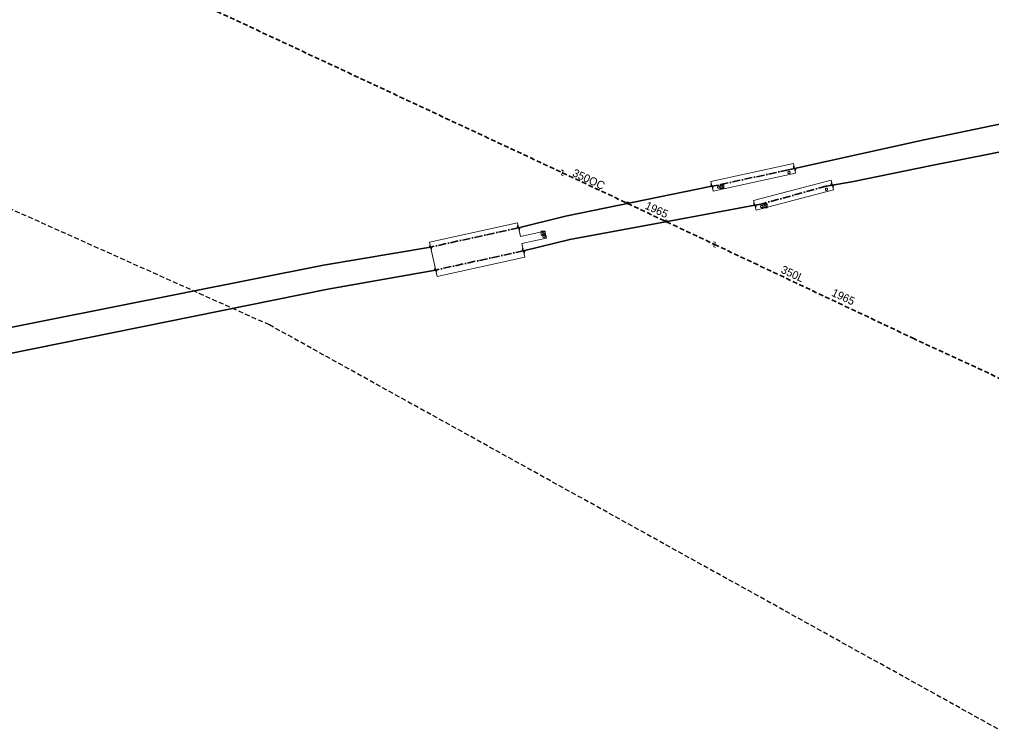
# Model space of a CAD drawing. Extents: x -735085 to -733500, y -1044153 to -1043402.
# Drawn here: x -734295.8 to -734101.4, y -1043978.5 to -1043837.5 of the extents above; entities that cross this region are included whole.
import ezdxf

# ---------------------------------------------------------------- set-up
doc = ezdxf.new("R2010")
doc.units = 0
doc.header["$LTSCALE"] = 0.32
doc.linetypes.add('DOT_DASHED', pattern=[7.7, 5, -1.2, 0.3, -1.2])
doc.linetypes.add('MEDIUM_DASHED', pattern=[4.5, 3, -1.5])
doc.layers.add('15', color=7, linetype='Continuous')
doc.layers.add('63', color=7, linetype='MEDIUM_DASHED', lineweight=25)
doc.layers.add('8', color=7, linetype='Continuous', lineweight=13)

msp = doc.modelspace()

# ---------------------------------------------------------------- linework, layer by layer
at = {"layer": '63'}
msp.add_lwpolyline([(-733848.634, -1044145.724), (-734009.504, -1044029.598), (-734245.816, -1043898.575), (-734359.738, -1043847.543)], dxfattribs=at)
at = {"layer": '8', "linetype": 'MEDIUM_DASHED', "lineweight": 35}
msp.add_line((-734187.217, -1043868.148), (-734156.787, -1043882.494), dxfattribs=at)
at = {"layer": '8', "linetype": 'DOT_DASHED', "lineweight": 35}
for p, q in [((-734196, -1043879.15), (-734213.581, -1043883.01)), ((-734194.993, -1043883.74), (-734212.574, -1043887.601))]:
    msp.add_line(p, q, dxfattribs=at)
at = {"layer": '8', "linetype": 'MEDIUM_DASHED', "lineweight": 35}
for points in [[(-734536.445, -1043703.656), (-734437.539, -1043750.071), (-734375.002, -1043779.659), (-734325.456, -1043803.606), (-734187.217, -1043868.148)], [(-734156.787, -1043882.494), (-734117.203, -1043901.187), (-734043.806, -1043935.179), (-734015.348, -1043948.221), (-733950.381, -1043983.651), (-733846.87, -1044026.74)]]:
    msp.add_lwpolyline(points, dxfattribs=at)
at = {"layer": '8', "lineweight": 35}
for points in [[(-733500.14, -1043736.5), (-733578.17, -1043751.88), (-733749.774, -1043785.92), (-733782.129, -1043791.12), (-733828.849, -1043802.13), (-733843.715, -1043805.114), (-734013.309, -1043840.11), (-734084.403, -1043855.21), (-734114.903, -1043861.54), (-734140.791, -1043867.289)], [(-733499.8, -1043741.34), (-733577.602, -1043756.92), (-733749.741, -1043791.62), (-733780.166, -1043797.47), (-733830.039, -1043807.22), (-733842.373, -1043809.844), (-733894.938, -1043820.77), (-733957.55, -1043834.01), (-734011.796, -1043845.47), (-734062.127, -1043856.17), (-734083.072, -1043860.7), (-734113.399, -1043866.69), (-734129.342, -1043869.95), (-734133.254, -1043870.63)], [(-734157.313, -1043870.86), (-734186.633, -1043876.84), (-734196, -1043879.15)], [(-734148.727, -1043874.66), (-734162.243, -1043877.147), (-734185.761, -1043881.48), (-734194.991, -1043883.74)], [(-734213.581, -1043883.01), (-734235.013, -1043886.65), (-734347.918, -1043909.08), (-734406.037, -1043923.44), (-734576.715, -1043958.74), (-734576.97, -1043958.792)], [(-734212.574, -1043887.6), (-734234.101, -1043891.43), (-734346.778, -1043914.23), (-734403.784, -1043928.54), (-734524.885, -1043953.44), (-734575.754, -1043964.068), (-734576.02, -1043964.124)]]:
    msp.add_lwpolyline(points, dxfattribs=at)
at = {"layer": '8'}
for points in [[(-734187.432, -1043867.587), (-734187.038, -1043867.771), (-734187.406, -1043868.557), (-734187.012, -1043868.741)], [(-734141.037, -1043867.266), (-734140.988, -1043866.827), (-734140.608, -1043867.714), (-734140.53, -1043867.316)], [(-734157.558, -1043870.832), (-734157.501, -1043870.393), (-734157.136, -1043871.287), (-734157.051, -1043870.89)], [(-734155.474, -1043871.104), (-734155.464, -1043871.147), (-734155.442, -1043871.186), (-734155.411, -1043871.217), (-734155.373, -1043871.238), (-734155.33, -1043871.249), (-734155.286, -1043871.247), (-734155.244, -1043871.234), (-734155.207, -1043871.21), (-734155.178, -1043871.177), (-734155.159, -1043871.137), (-734155.151, -1043871.094), (-734155.155, -1043871.05), (-734155.171, -1043871.009), (-734155.197, -1043870.974), (-734155.232, -1043870.947), (-734155.273, -1043870.93), (-734155.299, -1043870.925)], [(-734155.152, -1043870.767), (-734155.157, -1043870.724), (-734155.174, -1043870.683), (-734155.201, -1043870.649), (-734155.237, -1043870.623), (-734155.278, -1043870.608), (-734155.321, -1043870.605), (-734155.364, -1043870.613), (-734155.403, -1043870.633), (-734155.436, -1043870.662), (-734155.459, -1043870.7), (-734155.471, -1043870.742), (-734155.472, -1043870.785), (-734155.46, -1043870.828), (-734155.438, -1043870.865), (-734155.406, -1043870.896), (-734155.368, -1043870.916), (-734155.325, -1043870.925), (-734155.299, -1043870.925)], [(-734133.01, -1043870.664), (-734133.08, -1043871.1), (-734133.417, -1043870.195), (-734133.515, -1043870.59)], [(-734173.907, -1043874.439), (-734173.894, -1043874.41), (-734173.886, -1043874.379), (-734173.879, -1043874.348), (-734173.878, -1043874.317), (-734173.879, -1043874.286), (-734173.883, -1043874.253), (-734173.891, -1043874.223), (-734173.901, -1043874.192), (-734173.915, -1043874.164), (-734173.932, -1043874.137), (-734173.951, -1043874.112), (-734173.973, -1043874.088), (-734173.997, -1043874.068), (-734174.024, -1043874.05), (-734174.051, -1043874.035), (-734174.081, -1043874.023), (-734174.111, -1043874.015), (-734174.143, -1043874.009), (-734174.175, -1043874.007), (-734174.206, -1043874.008), (-734174.238, -1043874.011), (-734174.269, -1043874.019), (-734174.3, -1043874.03), (-734174.327, -1043874.043), (-734174.355, -1043874.061), (-734174.38, -1043874.08), (-734174.403, -1043874.102), (-734174.424, -1043874.126), (-734174.441, -1043874.152), (-734174.456, -1043874.181)], [(-734148.972, -1043874.627), (-734148.908, -1043874.19), (-734148.558, -1043875.09), (-734148.466, -1043874.695)], [(-734146.823, -1043874.946), (-734146.813, -1043874.989), (-734146.791, -1043875.028), (-734146.76, -1043875.059), (-734146.722, -1043875.08), (-734146.679, -1043875.091), (-734146.635, -1043875.089), (-734146.593, -1043875.076), (-734146.556, -1043875.052), (-734146.527, -1043875.019), (-734146.508, -1043874.979), (-734146.5, -1043874.936), (-734146.504, -1043874.892), (-734146.52, -1043874.851), (-734146.546, -1043874.816), (-734146.581, -1043874.789), (-734146.622, -1043874.772), (-734146.647, -1043874.767)], [(-734146.5, -1043874.609), (-734146.505, -1043874.566), (-734146.522, -1043874.525), (-734146.549, -1043874.491), (-734146.586, -1043874.465), (-734146.627, -1043874.45), (-734146.67, -1043874.447), (-734146.713, -1043874.455), (-734146.752, -1043874.475), (-734146.785, -1043874.504), (-734146.808, -1043874.542), (-734146.82, -1043874.584), (-734146.821, -1043874.627), (-734146.809, -1043874.67), (-734146.787, -1043874.707), (-734146.755, -1043874.738), (-734146.717, -1043874.758), (-734146.674, -1043874.767), (-734146.647, -1043874.767)], [(-734195.753, -1043879.166), (-734195.791, -1043879.606), (-734196.193, -1043878.728), (-734196.262, -1043879.128)], [(-734166.21, -1043878.068), (-734166.197, -1043878.039), (-734166.189, -1043878.008), (-734166.182, -1043877.977), (-734166.181, -1043877.946), (-734166.182, -1043877.915), (-734166.186, -1043877.882), (-734166.194, -1043877.852), (-734166.204, -1043877.821), (-734166.218, -1043877.793), (-734166.235, -1043877.766), (-734166.254, -1043877.741), (-734166.276, -1043877.717), (-734166.3, -1043877.697), (-734166.327, -1043877.679), (-734166.354, -1043877.664), (-734166.384, -1043877.652), (-734166.414, -1043877.644), (-734166.446, -1043877.638), (-734166.478, -1043877.636), (-734166.509, -1043877.637), (-734166.541, -1043877.64), (-734166.572, -1043877.648), (-734166.603, -1043877.659), (-734166.63, -1043877.672), (-734166.658, -1043877.69), (-734166.683, -1043877.709), (-734166.706, -1043877.731), (-734166.727, -1043877.755), (-734166.744, -1043877.781), (-734166.759, -1043877.81)], [(-734191.222, -1043880.416), (-734191.212, -1043880.459), (-734191.19, -1043880.498), (-734191.159, -1043880.529), (-734191.12, -1043880.55), (-734191.078, -1043880.561), (-734191.034, -1043880.559), (-734190.992, -1043880.546), (-734190.955, -1043880.522), (-734190.926, -1043880.489), (-734190.907, -1043880.449), (-734190.899, -1043880.406), (-734190.902, -1043880.362), (-734190.919, -1043880.321), (-734190.945, -1043880.286), (-734190.98, -1043880.259), (-734191.021, -1043880.242), (-734191.046, -1043880.237)], [(-734190.899, -1043880.079), (-734190.904, -1043880.036), (-734190.921, -1043879.995), (-734190.948, -1043879.961), (-734190.985, -1043879.935), (-734191.026, -1043879.92), (-734191.069, -1043879.917), (-734191.112, -1043879.925), (-734191.151, -1043879.945), (-734191.184, -1043879.974), (-734191.206, -1043880.012), (-734191.218, -1043880.054), (-734191.22, -1043880.097), (-734191.208, -1043880.14), (-734191.186, -1043880.177), (-734191.154, -1043880.208), (-734191.115, -1043880.228), (-734191.073, -1043880.237), (-734191.046, -1043880.237)], [(-734213.825, -1043882.974), (-734213.755, -1043882.538), (-734213.418, -1043883.443), (-734213.32, -1043883.049)], [(-734194.746, -1043883.758), (-734194.786, -1043884.198), (-734195.184, -1043883.318), (-734195.255, -1043883.718)], [(-734157.002, -1043881.932), (-734156.609, -1043882.117), (-734156.979, -1043882.902), (-734156.587, -1043883.087)], [(-734212.818, -1043887.566), (-734212.752, -1043887.129), (-734212.407, -1043888.031), (-734212.313, -1043887.636)]]:
    msp.add_lwpolyline(points, dxfattribs=at)
for points in [[(-734140.581, -1043868.267), (-734141.002, -1043866.313), (-734157.524, -1043869.883), (-734157.103, -1043871.837)], [(-734141.679, -1043868.098), (-734141.686, -1043868.046), (-734141.703, -1043867.996), (-734141.732, -1043867.952), (-734141.77, -1043867.915), (-734141.815, -1043867.888), (-734141.865, -1043867.872), (-734141.917, -1043867.867), (-734141.968, -1043867.874), (-734142.017, -1043867.893), (-734142.061, -1043867.923), (-734142.097, -1043867.962), (-734142.123, -1043868.007), (-734142.137, -1043868.058), (-734142.141, -1043868.11), (-734142.132, -1043868.162), (-734142.112, -1043868.21), (-734142.081, -1043868.253), (-734142.042, -1043868.288), (-734141.995, -1043868.312), (-734141.945, -1043868.326), (-734141.892, -1043868.328), (-734141.841, -1043868.318), (-734141.793, -1043868.296), (-734141.75, -1043868.264), (-734141.718, -1043868.224), (-734141.694, -1043868.177), (-734141.681, -1043868.126)], [(-734148.978, -1043873.692), (-734148.475, -1043875.628), (-734133.002, -1043871.598), (-734133.506, -1043869.662)], [(-734155.744, -1043871.033), (-734155.75, -1043870.981), (-734155.767, -1043870.931), (-734155.796, -1043870.887), (-734155.834, -1043870.85), (-734155.879, -1043870.823), (-734155.929, -1043870.807), (-734155.981, -1043870.802), (-734156.032, -1043870.809), (-734156.081, -1043870.828), (-734156.125, -1043870.858), (-734156.161, -1043870.897), (-734156.187, -1043870.942), (-734156.201, -1043870.993), (-734156.205, -1043871.045), (-734156.196, -1043871.097), (-734156.176, -1043871.145), (-734156.146, -1043871.188), (-734156.106, -1043871.223), (-734156.059, -1043871.247), (-734156.009, -1043871.261), (-734155.956, -1043871.263), (-734155.905, -1043871.253), (-734155.857, -1043871.231), (-734155.815, -1043871.199), (-734155.782, -1043871.159), (-734155.758, -1043871.112), (-734155.745, -1043871.061)], [(-734155.701, -1043870.521), (-734154.911, -1043870.521), (-734154.911, -1043871.321), (-734155.701, -1043871.321)], [(-734134.179, -1043871.456), (-734134.185, -1043871.404), (-734134.203, -1043871.354), (-734134.231, -1043871.31), (-734134.269, -1043871.273), (-734134.314, -1043871.246), (-734134.364, -1043871.23), (-734134.416, -1043871.225), (-734134.468, -1043871.232), (-734134.517, -1043871.251), (-734134.561, -1043871.281), (-734134.596, -1043871.32), (-734134.622, -1043871.365), (-734134.637, -1043871.416), (-734134.64, -1043871.468), (-734134.632, -1043871.52), (-734134.611, -1043871.568), (-734134.581, -1043871.611), (-734134.541, -1043871.646), (-734134.495, -1043871.67), (-734134.444, -1043871.684), (-734134.392, -1043871.686), (-734134.34, -1043871.676), (-734134.292, -1043871.654), (-734134.25, -1043871.622), (-734134.217, -1043871.582), (-734134.193, -1043871.535), (-734134.181, -1043871.484)], [(-734147.124, -1043874.905), (-734147.13, -1043874.853), (-734147.147, -1043874.803), (-734147.176, -1043874.759), (-734147.214, -1043874.722), (-734147.259, -1043874.695), (-734147.309, -1043874.679), (-734147.361, -1043874.674), (-734147.413, -1043874.681), (-734147.462, -1043874.7), (-734147.505, -1043874.73), (-734147.541, -1043874.769), (-734147.567, -1043874.814), (-734147.581, -1043874.865), (-734147.585, -1043874.917), (-734147.576, -1043874.969), (-734147.556, -1043875.017), (-734147.526, -1043875.06), (-734147.486, -1043875.095), (-734147.44, -1043875.119), (-734147.389, -1043875.133), (-734147.337, -1043875.135), (-734147.285, -1043875.125), (-734147.237, -1043875.103), (-734147.195, -1043875.071), (-734147.162, -1043875.031), (-734147.138, -1043874.984), (-734147.125, -1043874.933)], [(-734147.049, -1043874.363), (-734146.26, -1043874.363), (-734146.26, -1043875.163), (-734147.049, -1043875.163)], [(-734213.796, -1043882.03), (-734212.295, -1043888.87), (-734194.714, -1043885.01), (-734195.313, -1043882.27), (-734190.43, -1043881.2), (-734190.73, -1043879.83), (-734195.614, -1043880.91), (-734196.215, -1043878.17)], [(-734191.448, -1043879.833), (-734190.659, -1043879.833), (-734190.659, -1043880.633), (-734191.448, -1043880.633)], [(-734190.678, -1043880.878), (-734190.684, -1043880.826), (-734190.701, -1043880.776), (-734190.73, -1043880.732), (-734190.768, -1043880.695), (-734190.813, -1043880.668), (-734190.863, -1043880.652), (-734190.915, -1043880.647), (-734190.967, -1043880.654), (-734191.016, -1043880.673), (-734191.059, -1043880.703), (-734191.095, -1043880.742), (-734191.121, -1043880.787), (-734191.136, -1043880.838), (-734191.139, -1043880.89), (-734191.13, -1043880.942), (-734191.11, -1043880.99), (-734191.08, -1043881.033), (-734191.04, -1043881.068), (-734190.994, -1043881.092), (-734190.943, -1043881.106), (-734190.891, -1043881.108), (-734190.839, -1043881.098), (-734190.791, -1043881.076), (-734190.749, -1043881.044), (-734190.716, -1043881.004), (-734190.692, -1043880.957), (-734190.679, -1043880.906)]]:
    msp.add_lwpolyline(points, close=True, dxfattribs=at)
at = {"layer": '8', "linetype": 'DOT_DASHED', "lineweight": 35}
for points in [[(-734140.791, -1043867.29), (-734142.011, -1043867.56), (-734156.089, -1043870.61), (-734157.313, -1043870.86)], [(-734133.254, -1043870.63), (-734134.487, -1043870.84), (-734147.497, -1043874.429), (-734148.727, -1043874.66)]]:
    msp.add_lwpolyline(points, dxfattribs=at)

# ---------------------------------------------------------------- texts
at = {"layer": '15'}
for s, p in [('350OC ', (-734185.365, -1043868.741)), ('1965', (-734170.85, -1043875.266)), ('350L', (-734143.684, -1043888.073)), ('1965', (-734133.534, -1043892.687))]:
    msp.add_text(s, height=1.6, rotation=335, dxfattribs=at).set_placement(p)

doc.saveas('drawing.dxf')
